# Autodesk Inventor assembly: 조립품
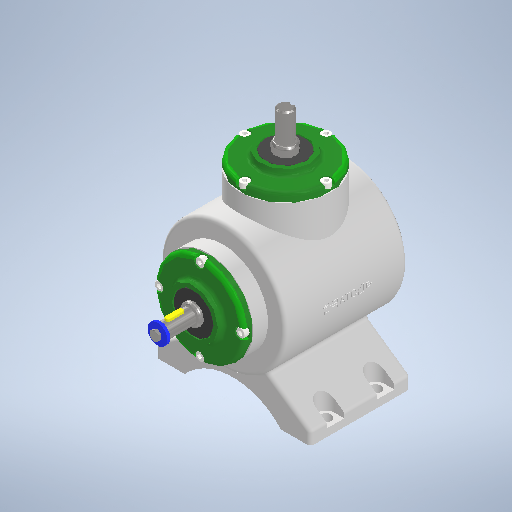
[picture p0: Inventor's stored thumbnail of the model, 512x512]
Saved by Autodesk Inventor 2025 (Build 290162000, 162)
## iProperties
Created: 2024-07
Part Number: 조립품
Document SubType Name: Assembly
Designer: hsj03
Author: hsj03
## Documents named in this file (15)
- C:\Users\hsj03\OneDrive\바탕 화면\740709V1007\조립품.iam
- C:\Users\hsj03\OneDrive\바탕 화면\740709V1007\본체.ipt
- C:\Users\hsj03\OneDrive\바탕 화면\740709V1007\V-벨트풀리\V-벨트풀리.ipt
- C:\Users\hsj03\OneDrive\바탕 화면\740709V1007\메인 베벨기어\메인 베벨기어.ipt
- C:\Users\hsj03\OneDrive\바탕 화면\740709V1007\메인 축\메인 축.ipt
- C:\Users\hsj03\OneDrive\바탕 화면\740709V1007\베어링 6203\베어링 6203.ipt
- C:\Users\hsj03\OneDrive\바탕 화면\740709V1007\볼트 M4 x 10\볼트 M4 x 10.ipt
- C:\Users\hsj03\OneDrive\바탕 화면\740709V1007\서브 베벨기어\서브 베벨기어.ipt
- C:\Users\hsj03\OneDrive\바탕 화면\740709V1007\서브 축\서브 축.ipt
- C:\Users\hsj03\OneDrive\바탕 화면\740709V1007\오일실 17 x 32 x 8\오일실 17 x 32 x 8.ipt
- C:\Users\hsj03\OneDrive\바탕 화면\740709V1007\와셔 4 x 16\와셔 4 x 16.ipt
- C:\Users\hsj03\OneDrive\바탕 화면\740709V1007\육각볼트 M4 x 8\육각볼트 M4 x 8.ipt
- C:\Users\hsj03\OneDrive\바탕 화면\740709V1007\커버\커버.ipt
- C:\Users\hsj03\OneDrive\바탕 화면\740709V1007\키 4 x 4 x 14\키 4 x 4 x 14.ipt
- C:\Users\hsj03\OneDrive\바탕 화면\740709V1007\키 5 x 5 x 14\키 5 x 5 x 14.ipt
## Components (1 placed, 1 different names)
1. V-벨트풀리:1
